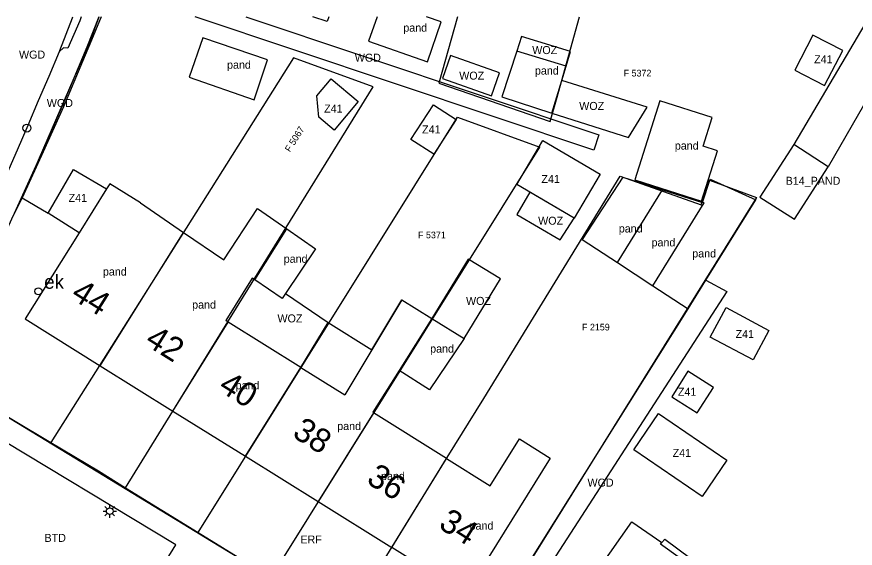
# Model space of a CAD drawing. Extents: x 198240 to 198429, y 356553 to 356721.
# Drawn here: x 198326.7 to 198389.6, y 356680.8 to 356720.6 of the extents above; entities that cross this region are included whole.
import ezdxf

# ---------------------------------------------------------------- set-up
doc = ezdxf.new("R2010")
doc.units = 0
for name, color, linetype in [('(presentatie) Code GPNDDECOM (lijn of vlak) (zonder attributen) niet in de presentatietabel', 7, 'Continuous'), ('begroeid terreindeel kenmerkpunt', 7, 'Continuous'), ('bijgebouw', 7, 'Continuous'), ('Elektrakast', 7, 'Continuous'), ('Grens maaiveld', 7, 'Continuous'), ('grens WOZ object', 7, 'Continuous'), ('hoofdgebouw', 7, 'Continuous'), ('huisnummerreeks BGT', 7, 'Continuous'), ('identificerend kenmerkpunt bijpand', 7, 'Continuous'), ('identificerend kenmerkpunt pand', 7, 'Continuous'), ('identificerend kenmerkpunt WOZ object', 7, 'Continuous'), ('kant verharding', 7, 'Continuous'), ('kolk', 7, 'Continuous'), ('LICHTMAST', 7, 'Continuous'), ('onbegroeid terreindeel kenmerkpunt', 7, 'Continuous'), ('Perceelnummer', 7, 'Continuous'), ('perceelsgrens_definitief', 7, 'Continuous'), ('schutting geen IMGeo', 7, 'Continuous'), ('tussenmuur', 7, 'Continuous'), ('tussenmuur bijgebouw (GBKN Zuid)', 7, 'Continuous'), ('wegdeel kenmerkpunt', 7, 'Continuous')]:
    doc.layers.add(name, color=color, linetype=linetype)

msp = doc.modelspace()

# ---------------------------------------------------------------- linework, layer by layer
at = {"layer": '(presentatie) Code GPNDDECOM (lijn of vlak) (zonder attributen) niet in de presentatietabel'}
for p in [(198355.543, 356699.385), (198347.988, 356694.308)]:
    msp.add_line(p, (198351.269, 356692.261), dxfattribs=at)
msp.add_lwpolyline([(198375.042, 356681.183), (198375.278, 356681.425), (198378.209, 356679.263)], dxfattribs=at)
at = {"layer": 'bijgebouw'}
for p, q in [((198386.376, 356719.256), (198385.018, 356716.616)), ((198388.623, 356718.101), (198386.376, 356719.256)), ((198367.88, 356716.925), (198364.183, 356718.054)), ((198387.265, 356715.46), (198388.623, 356718.101)), ((198367.55, 356715.844), (198367.88, 356716.925)), ((198385.018, 356716.616), (198387.265, 356715.46)), ((198349.176, 356714.698), (198350.252, 356715.974)), ((198350.252, 356715.974), (198352.278, 356714.267)), ((198366.802, 356713.394), (198367.55, 356715.844)), ((198349.328, 356713.088), (198349.176, 356714.698)), ((198352.278, 356714.267), (198350.472, 356712.124)), ((198356.241, 356711.421), (198357.918, 356714.026)), ((198357.918, 356714.026), (198359.63, 356712.923)), ((198350.472, 356712.124), (198349.328, 356713.088)), ((198359.63, 356712.923), (198357.952, 356710.319)), ((198357.952, 356710.319), (198356.241, 356711.421)), ((198364.18, 356708.046), (198366.118, 356711.348)), ((198366.118, 356711.348), (198370.427, 356708.819)), ((198384.945, 356711.036), (198382.412, 356707.1)), ((198387.535, 356709.369), (198384.945, 356711.036)), ((198370.427, 356708.819), (198368.489, 356705.517)), ((198372.133, 356708.603), (198375.111, 356707.655)), ((198368.489, 356705.517), (198364.18, 356708.046)), ((198375.111, 356707.655), (198378.113, 356706.7)), ((198378.362, 356700.859), (198382.097, 356706.896)), ((198331.344, 356704.418), (198329.03, 356705.902)), ((198371.725, 356702.182), (198374.38, 356700.448)), ((198377.035, 356698.715), (198378.362, 356700.859)), ((198374.38, 356700.448), (198377.035, 356698.715)), ((198378.687, 356696.598), (198379.874, 356698.81)), ((198379.874, 356698.81), (198383.081, 356697.089)), ((198383.081, 356697.089), (198381.894, 356694.877)), ((198381.894, 356694.877), (198378.687, 356696.598)), ((198377.005, 356694.029), (198375.795, 356692.12)), ((198378.92, 356692.814), (198377.005, 356694.029)), ((198377.71, 356690.906), (198378.92, 356692.814)), ((198375.795, 356692.12), (198377.71, 356690.906)), ((198372.946, 356688.132), (198374.798, 356690.859)), ((198374.798, 356690.859), (198379.941, 356687.367)), ((198378.09, 356684.64), (198372.946, 356688.132)), ((198379.941, 356687.367), (198378.09, 356684.64))]:
    msp.add_line(p, q, dxfattribs=at)
for points in [[(198353.7, 356720.628), (198353.055, 356718.795), (198357.469, 356717.243), (198358.493, 356720.256), (198357.398, 356720.628)], [(198344.477, 356714.393), (198345.491, 356717.408), (198340.637, 356719.04), (198339.607, 356716.099), (198344.477, 356714.393)], [(198364.183, 356718.054), (198363.063, 356714.61), (198366.802, 356713.394)], [(198378.036, 356706.788), (198379.241, 356710.579), (198378.158, 356710.923), (198378.84, 356713.066), (198374.906, 356714.317), (198373.018, 356708.385), (198378.036, 356706.788)], [(198329.03, 356705.902), (198330.923, 356709.157), (198333.402, 356707.715)], [(198382.412, 356707.1), (198385.002, 356705.433), (198387.535, 356709.369)], [(198372.133, 356708.603), (198369.072, 356703.914), (198371.725, 356702.182)], [(198378.113, 356706.7), (198378.671, 356708.454), (198382.097, 356706.896)], [(198346.918, 356704.727), (198349.072, 356703.222), (198346.823, 356699.853)], [(198346.823, 356699.853), (198346.582, 356699.492), (198344.518, 356700.881)], [(198357.794, 356697.996), (198360.22, 356696.5), (198357.62, 356692.628), (198355.349, 356694.077)]]:
    msp.add_lwpolyline(points, dxfattribs=at)
at = {"layer": 'Elektrakast'}
msp.add_circle((198328.304, 356700.029), 0.263, dxfattribs=at)
msp.add_circle((198328.304, 356700.029), 0.263, dxfattribs=at)
at = {"layer": 'Grens maaiveld'}
msp.add_line((198355.543, 356699.385), (198357.794, 356697.996), dxfattribs=at)
for points in [[(198392.443, 356720.628), (198392.198, 356720.187), (198393.31, 356719.404), (198387.535, 356709.369)], [(198350.018, 356697.69), (198353.298, 356695.644), (198355.543, 356699.385)], [(198371.628, 356669.894), (198366.378, 356673.581), (198372.816, 356682.746), (198375.042, 356681.183)], [(198375.985, 356676.097), (198377.965, 356678.916), (198374.951, 356681.05), (198375.042, 356681.183)]]:
    msp.add_lwpolyline(points, dxfattribs=at)
at = {"layer": 'grens WOZ object'}
for p, q in [((198364.537, 356719.144), (198364.183, 356718.054)), ((198365.16, 356707.47), (198364.187, 356705.782)), ((198368.489, 356705.517), (198365.16, 356707.47)), ((198364.187, 356705.782), (198367.433, 356703.893)), ((198367.433, 356703.893), (198368.489, 356705.517)), ((198346.823, 356699.853), (198350.018, 356697.69)), ((198347.988, 356694.308), (198350.018, 356697.69))]:
    msp.add_line(p, q, dxfattribs=at)
for points in [[(198367.88, 356716.925), (198368.215, 356718.021), (198364.537, 356719.144)], [(198362.278, 356714.706), (198362.885, 356716.431), (198359.2, 356717.728), (198358.593, 356716.003), (198362.278, 356714.706)], [(198366.802, 356713.394), (198372.545, 356711.579), (198373.956, 356713.84), (198367.55, 356715.844)], [(198357.794, 356697.996), (198360.22, 356696.5), (198362.966, 356700.953), (198360.54, 356702.449), (198357.794, 356697.996)]]:
    msp.add_lwpolyline(points, dxfattribs=at)
at = {"layer": 'hoofdgebouw'}
for p, q in [((198333.402, 356707.715), (198331.344, 356704.418)), ((198335.953, 356706.663), (198339.175, 356704.453)), ((198342.538, 356697.709), (198342.349, 356697.827)), ((198347.988, 356694.308), (198342.538, 356697.709)), ((198332.932, 356694.45), (198338.382, 356691.049)), ((198355.349, 356694.077), (198353.369, 356690.95)), ((198338.382, 356691.049), (198343.831, 356687.648)), ((198353.437, 356690.908), (198353.369, 356690.95)), ((198358.909, 356687.493), (198353.437, 356690.908)), ((198343.831, 356687.648), (198349.281, 356684.247)), ((198349.281, 356684.247), (198354.799, 356680.803))]:
    msp.add_line(p, q, dxfattribs=at)
for points in [[(198350.072, 356720.628), (198349.952, 356720.269), (198348.878, 356720.628)], [(198335.953, 356706.663), (198333.644, 356708.103), (198333.402, 356707.715)], [(198339.175, 356704.453), (198342.197, 356702.38), (198344.733, 356706.255), (198346.918, 356704.727)], [(198331.344, 356704.418), (198327.313, 356697.957), (198332.932, 356694.45)], [(198344.518, 356700.881), (198344.327, 356701.009), (198342.349, 356697.827)], [(198358.909, 356687.493), (198362.19, 356685.446), (198364.369, 356688.955), (198366.68, 356687.52), (198360.355, 356677.335), (198354.799, 356680.803)]]:
    msp.add_lwpolyline(points, dxfattribs=at)
at = {"layer": 'kant verharding'}
for p, q in [((198327.071, 356707.032), (198332.199, 356718.866)), ((198362.69, 356675.866), (198377.035, 356698.715))]:
    msp.add_line(p, q, dxfattribs=at)
for points in [[(198331.504, 356720.628), (198331.394, 356720.335), (198330.505, 356718.264), (198330.174, 356718.299), (198329.869, 356718.018)], [(198329.869, 356718.018), (198329.898, 356718.088), (198330.858, 356720.547), (198330.89, 356720.628)], [(198332.199, 356718.866), (198332.862, 356720.628)], [(198343.846, 356720.628), (198370.325, 356711.772), (198369.963, 356710.613), (198340.043, 356720.628)], [(198390.591, 356720.628), (198384.945, 356711.036)], [(198317.861, 356691.51), (198323.84, 356704.262), (198324.269, 356705.183), (198325.106, 356706.997), (198325.925, 356708.813), (198326.734, 356710.653), (198327.521, 356712.488), (198328.316, 356714.335), (198329.102, 356716.178), (198329.869, 356718.018)], [(198320.873, 356693.711), (198325.431, 356703.505), (198326.306, 356705.459), (198327.071, 356707.032)], [(198378.362, 356700.859), (198379.92, 356700.023), (198363.843, 356675.152)], [(198325.044, 356691.174), (198339.161, 356682.588), (198341.279, 356681.288), (198343.379, 356680.014), (198351.339, 356675.001), (198352.823, 356674.056), (198356.526, 356671.657), (198358.554, 356670.367), (198359.064, 356670.025)], [(198333.616, 356672.898), (198338.593, 356680.997), (198324.168, 356689.714)]]:
    msp.add_lwpolyline(points, dxfattribs=at)
at = {"layer": 'kolk'}
msp.add_circle((198327.437, 356712.28), 0.3, dxfattribs=at)
at = {"layer": 'LICHTMAST'}
for p, q in [((198333.468, 356683.707), (198333.291, 356683.884)), ((198333.645, 356683.78), (198333.645, 356684.03)), ((198333.822, 356683.707), (198333.999, 356683.884)), ((198333.145, 356683.53), (198333.395, 356683.53)), ((198333.291, 356683.176), (198333.468, 356683.353)), ((198333.645, 356683.03), (198333.645, 356683.28)), ((198333.999, 356683.176), (198333.822, 356683.353)), ((198333.895, 356683.53), (198334.145, 356683.53))]:
    msp.add_line(p, q, dxfattribs=at)
msp.add_circle((198333.645, 356683.53), 0.25, dxfattribs=at)
at = {"layer": 'perceelsgrens_definitief'}
for points in [[(198332.837, 356720.628), (198331.931, 356718.35), (198330.183, 356714.16), (198328.366, 356709.999), (198326.48, 356705.869)], [(198359.731, 356720.628), (198358.326, 356715.651), (198366.676, 356712.762), (198367.163, 356714.422), (198368.884, 356720.628)], [(198353.397, 356715.382), (198347.434, 356717.544), (198337.078, 356701.116), (198332.892, 356694.475), (198329.236, 356688.676)], [(198334.837, 356685.292), (198338.386, 356691.046), (198342.508, 356697.728), (198353.397, 356715.382)], [(198340.281, 356681.925), (198359.729, 356713.085)], [(198359.729, 356713.085), (198365.905, 356710.845)], [(198345.747, 356678.545), (198365.905, 356710.845)], [(198351.308, 356675.119), (198358.955, 356687.569), (198361.716, 356691.988), (198371.934, 356708.659)], [(198371.934, 356708.659), (198378.011, 356706.528), (198378.641, 356708.364), (198382.147, 356707.061), (198359.148, 356670.092)], [(198320.807, 356693.703), (198329.236, 356688.676)], [(198329.236, 356688.676), (198332.797, 356686.553), (198334.837, 356685.292)], [(198334.837, 356685.292), (198340.281, 356681.925)], [(198340.281, 356681.925), (198345.747, 356678.545)]]:
    msp.add_lwpolyline(points, dxfattribs=at)
at = {"layer": 'schutting geen IMGeo'}
for points in [[(198333.018, 356720.628), (198332.279, 356718.869)], [(198332.279, 356718.869), (198331.597, 356717.277), (198330.19, 356713.858), (198328.668, 356710.506), (198327.071, 356707.032), (198329.03, 356705.902)]]:
    msp.add_lwpolyline(points, dxfattribs=at)
at = {"layer": 'tussenmuur'}
for p, q in [((198332.932, 356694.45), (198339.175, 356704.453)), ((198344.518, 356700.881), (198346.918, 356704.727)), ((198338.382, 356691.049), (198342.538, 356697.709)), ((198357.794, 356697.996), (198355.349, 356694.077)), ((198343.831, 356687.648), (198347.988, 356694.308)), ((198353.437, 356690.908), (198349.281, 356684.247)), ((198354.799, 356680.803), (198358.909, 356687.493))]:
    msp.add_line(p, q, dxfattribs=at)
at = {"layer": 'tussenmuur bijgebouw (GBKN Zuid)'}
msp.add_line((198371.725, 356702.182), (198375.111, 356707.655), dxfattribs=at)
msp.add_lwpolyline([(198374.38, 356700.448), (198378.225, 356706.664), (198378.113, 356706.7)], dxfattribs=at)

# ---------------------------------------------------------------- texts
at = {"layer": 'begroeid terreindeel kenmerkpunt'}
msp.add_text('BTD', height=0.6, dxfattribs=at).set_placement((198328.757, 356681.231))
at = {"layer": 'Elektrakast'}
msp.add_text('ek', height=1.05, dxfattribs=at).set_placement((198328.733, 356700.22))
at = {"layer": 'huisnummerreeks BGT'}
for s, p in [('44', (198330.643, 356699.534)), ('42', (198336.202, 356696.064)), ('40', (198341.713, 356692.626)), ('38', (198347.258, 356689.165)), ('36', (198352.818, 356685.694)), ('34', (198358.225, 356682.319))]:
    msp.add_text(s, height=1.8, rotation=328, dxfattribs=at).set_placement(p)
at = {"layer": 'identificerend kenmerkpunt bijpand'}
for s, p in [('pand', (198355.668, 356719.51)), ('Z41', (198386.476, 356717.143)), ('pand', (198342.448, 356716.73)), ('pand', (198365.538, 356716.29)), ('Z41', (198349.729, 356713.44)), ('Z41', (198357.075, 356711.878)), ('pand', (198376.028, 356710.66)), ('Z41', (198366.022, 356708.155)), ('B14_PAND', (198384.341, 356708.021)), ('Z41', (198330.563, 356706.742)), ('pand', (198371.826, 356704.442)), ('pand', (198374.282, 356703.398)), ('pand', (198377.336, 356702.569)), ('pand', (198346.698, 356702.17)), ('Z41', (198380.583, 356696.524)), ('pand', (198357.678, 356695.43)), ('Z41', (198376.26, 356692.195)), ('Z41', (198375.863, 356687.603))]:
    msp.add_text(s, height=0.6, dxfattribs=at).set_placement(p)
at = {"layer": 'identificerend kenmerkpunt pand'}
for p in [(198333.138, 356701.21), (198339.828, 356698.73), (198343.088, 356692.68), (198350.708, 356689.62), (198353.998, 356685.87), (198360.638, 356682.15)]:
    msp.add_text('pand', height=0.6, dxfattribs=at).set_placement(p)
at = {"layer": 'identificerend kenmerkpunt WOZ object'}
for p in [(198365.334, 356717.829), (198359.858, 356715.912), (198368.857, 356713.637), (198365.777, 356705.026), (198360.369, 356699.009), (198346.228, 356697.696)]:
    msp.add_text('WOZ', height=0.6, dxfattribs=at).set_placement(p)
at = {"layer": 'onbegroeid terreindeel kenmerkpunt'}
msp.add_text('ERF', height=0.6, dxfattribs=at).set_placement((198347.948, 356681.108))
at = {"layer": 'Perceelnummer'}
for s, p in [('F 5372', (198372.19, 356716.148)), ('F 5371', (198356.769, 356704.008)), ('F 2159', (198369.064, 356697.093))]:
    msp.add_text(s, height=0.5, dxfattribs=at).set_placement(p)
msp.add_text('F 5067', height=0.5, rotation=57.8, dxfattribs=at).set_placement((198347.168, 356710.438))
at = {"layer": 'wegdeel kenmerkpunt'}
for p in [(198326.843, 356717.49), (198352.025, 356717.257), (198328.928, 356713.856), (198369.479, 356685.375)]:
    msp.add_text('WGD', height=0.6, dxfattribs=at).set_placement(p)

doc.saveas('drawing.dxf')
